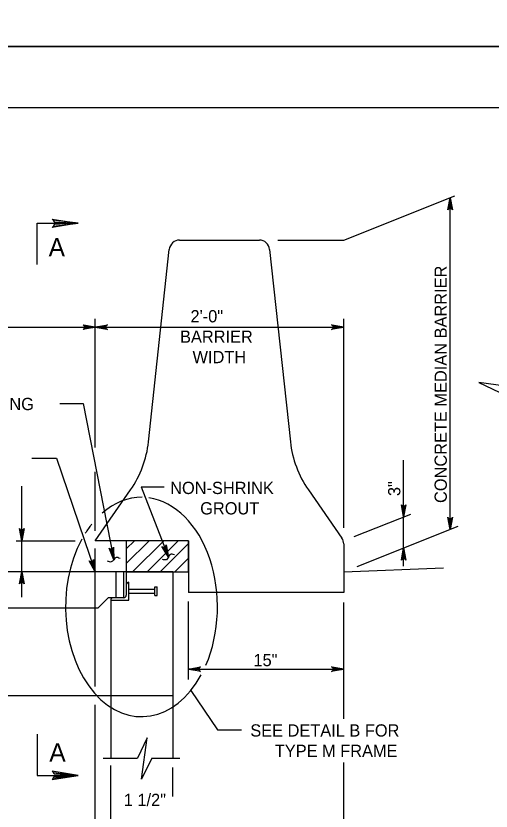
# Model space of a CAD drawing. Extents: x 2087776 to 2104538, y 970919 to 982612.
# Drawn here: x 2100038 to 2100420, y 976151 to 976790 of the extents above; entities that cross this region are included whole.
import ezdxf

# ---------------------------------------------------------------- set-up
doc = ezdxf.new("R2010")
doc.units = 0
doc.layers.add('1', color=7, linetype='Continuous')
doc.layers.add('PLT-BNDY', color=7, linetype='Continuous')

msp = doc.modelspace()

# ---------------------------------------------------------------- linework, layer by layer
at = {"layer": '1'}
for p, q in [((2100301.79, 976610.12), (2100391.14, 976645.62)), ((2100387.4, 976377.46), (2100387.4, 976644.13)), ((2100169.69, 976610.12), (2100233.89, 976610.12)), ((2100248.79, 976610.12), (2100301.79, 976610.12)), ((2100144.71, 976447.97), (2100161.41, 976602.68)), ((2100242.18, 976602.68), (2100258.88, 976447.97)), ((2100101.79, 976443.41), (2100101.79, 976546.94)), ((2100301.79, 976378.69), (2100301.79, 976546.94)), ((2099901.79, 976540.13), (2100101.79, 976540.13)), ((2100101.79, 976540.13), (2100301.79, 976540.13)), ((2100073.47, 976478.78), (2100092.2, 976478.78)), ((2100092.2, 976478.78), (2100116.73, 976353.17)), ((2100050.84, 976434.83), (2100070.67, 976434.83)), ((2100070.67, 976434.83), (2100101.79, 976343.45)), ((2100349.96, 976348.05), (2100349.96, 976433.16)), ((2100101.79, 976376.26), (2100101.79, 976423.89)), ((2100042.79, 976323.09), (2100042.79, 976412.2)), ((2100101.79, 976368.45), (2100130.24, 976409.29)), ((2100138.68, 976411.71), (2100157.42, 976411.71)), ((2100138.68, 976411.71), (2100160.69, 976355.3)), ((2100273.35, 976409.29), (2100300.3, 976370.59)), ((2100310.25, 976371.81), (2100355.72, 976389.88)), ((2100312.6, 976347.74), (2100393.93, 976380.06)), ((2100038.16, 976368.45), (2100085.61, 976368.45)), ((2100176.79, 976368.45), (2100101.79, 976368.45)), ((2100126.79, 976350.12), (2100145.12, 976368.45)), ((2100126.79, 976361.9), (2100133.34, 976368.45)), ((2100131.9, 976343.45), (2100156.9, 976368.45)), ((2100143.68, 976343.45), (2100168.68, 976368.45)), ((2100154.02, 976343.45), (2100176.79, 976366.22)), ((2100176.79, 976368.45), (2100176.79, 976326.78)), ((2100301.79, 976365.83), (2100301.79, 976326.78)), ((2100101.79, 976251.17), (2100101.79, 976362.06)), ((2100165.8, 976343.45), (2100176.79, 976354.44)), ((2100164.29, 976343.45), (2099864.29, 976343.45)), ((2100118.46, 976343.45), (2100118.46, 976322.61)), ((2100124.71, 976343.45), (2100124.71, 976322.61)), ((2100126.79, 976343.45), (2100126.79, 976333.03)), ((2100164.29, 976343.45), (2100164.29, 976193.61)), ((2100301.79, 976343.45), (2100382, 976346.66)), ((2100126.79, 976333.03), (2100126.79, 976324.7)), ((2100128.88, 976320.53), (2100128.88, 976335.11)), ((2100149.79, 976324.26), (2100149.79, 976331.38)), ((2100149.79, 976331.38), (2100151.79, 976331.38)), ((2100151.79, 976324.26), (2100151.79, 976331.38)), ((2100128.88, 976329.38), (2100149.79, 976329.38)), ((2100128.88, 976326.26), (2100149.79, 976326.26)), ((2100149.79, 976324.26), (2100151.79, 976324.26)), ((2100301.79, 976326.78), (2100176.79, 976326.78)), ((2100112.21, 976322.61), (2100103.88, 976314.28)), ((2100116.37, 976322.61), (2100112.21, 976322.61)), ((2100114.29, 976320.53), (2100114.29, 976243.61)), ((2100114.29, 976320.53), (2100128.88, 976320.53)), ((2100124.71, 976322.62), (2100116.37, 976322.62)), ((2100176.79, 976256.83), (2100176.79, 976319.66)), ((2100301.79, 976225.26), (2100301.79, 976318.83)), ((2100103.88, 976314.28), (2099924.7, 976314.28)), ((2100176.79, 976265.16), (2100301.79, 976265.16)), ((2100178.77, 976248.08), (2100200.09, 976216.49)), ((2100164.29, 976243.61), (2099864.29, 976243.61)), ((2100114.29, 976243.61), (2100114.29, 976193.61)), ((2100101.79, 976095.62), (2100101.79, 976236.51)), ((2100200.09, 976216.49), (2100219.59, 976216.49)), ((2100108.16, 976193.61), (2100135.94, 976193.61)), ((2100147.49, 976193.61), (2100169.85, 976193.61)), ((2100301.79, 976095.62), (2100301.79, 976190.11)), ((2100114.29, 976140.51), (2100114.29, 976187.81)), ((2100164.29, 976162.8), (2100164.29, 976186.07))]:
    msp.add_line(p, q, dxfattribs=at)
for points in [[(2101519.11, 974866.19), (2101519.11, 976716.58), (2098940.37, 976716.58), (2098940.37, 974866.19), (2101519.11, 974866.19), (2101519.11, 974952.67), (2100862.94, 974952.67), (2100862.94, 975164.86), (2101519.11, 975164.86), (2101519.11, 975259.89), (2100862.94, 975259.89), (2100862.94, 974866.19), (2101121.48, 974866.19), (2101121.48, 974952.67), (2101121.48, 974866.19), (2101374.1, 974866.19), (2101374.1, 974952.67), (2101374.1, 974912.26), (2101519.11, 974912.26)], [(2100387.4, 976644.13), (2100389.24, 976634.35), (2100388.98, 976634.73), (2100388.72, 976635.1), (2100388.39, 976635.3), (2100388.06, 976635.49), (2100387.73, 976635.55), (2100387.4, 976635.6), (2100387.08, 976635.55), (2100386.75, 976635.49), (2100386.42, 976635.3), (2100386.09, 976635.1), (2100385.83, 976634.73), (2100385.57, 976634.35), (2100387.4, 976644.13), (2100385.83, 976634.73), (2100386.09, 976635.1), (2100387.4, 976644.13), (2100386.42, 976635.3), (2100386.75, 976635.49), (2100387.4, 976644.13), (2100387.08, 976635.55), (2100387.4, 976635.6), (2100387.4, 976644.13), (2100387.73, 976635.55), (2100388.06, 976635.49), (2100387.4, 976644.13), (2100388.39, 976635.3), (2100388.72, 976635.1), (2100387.4, 976644.13), (2100388.98, 976634.73)], [(2100068.11, 976626.2), (2100068.86, 976624.76), (2100088.14, 976623.69), (2100068.11, 976626.2), (2100067.09, 976627.08), (2100088.14, 976623.69), (2100068.87, 976622.74), (2100068.17, 976621.3), (2100088.14, 976623.69), (2100067.09, 976620.35), (2100068.17, 976621.3)], [(2100055.06, 976590.62), (2100055.06, 976623.69), (2100088.14, 976623.69)], [(2100101.79, 976540.13), (2100092.01, 976538.29), (2100092.38, 976538.55), (2100092.76, 976538.81), (2100092.96, 976539.14), (2100093.15, 976539.47), (2100093.21, 976539.8), (2100093.26, 976540.13), (2100093.21, 976540.45), (2100093.15, 976540.78), (2100092.96, 976541.11), (2100092.76, 976541.44), (2100092.38, 976541.7), (2100092.01, 976541.96), (2100101.79, 976540.13), (2100092.38, 976541.7), (2100092.76, 976541.44), (2100101.79, 976540.13), (2100092.96, 976541.11), (2100093.15, 976540.78), (2100101.79, 976540.13), (2100093.21, 976540.45), (2100093.26, 976540.13), (2100101.79, 976540.13), (2100093.21, 976539.8), (2100093.15, 976539.47), (2100101.79, 976540.13), (2100092.96, 976539.14), (2100092.76, 976538.81), (2100101.79, 976540.13), (2100092.38, 976538.55)], [(2100101.79, 976540.13), (2100111.58, 976541.96), (2100111.2, 976541.7), (2100110.82, 976541.44), (2100110.63, 976541.11), (2100110.44, 976540.78), (2100110.38, 976540.45), (2100110.32, 976540.13), (2100110.38, 976539.8), (2100110.44, 976539.47), (2100110.63, 976539.14), (2100110.82, 976538.81), (2100111.2, 976538.55), (2100111.58, 976538.29), (2100101.79, 976540.13), (2100111.2, 976538.55), (2100110.82, 976538.81), (2100101.79, 976540.13), (2100110.63, 976539.14), (2100110.44, 976539.47), (2100101.79, 976540.13), (2100110.38, 976539.8), (2100110.32, 976540.13), (2100101.79, 976540.13), (2100110.38, 976540.45), (2100110.44, 976540.78), (2100101.79, 976540.13), (2100110.63, 976541.11), (2100110.82, 976541.44), (2100101.79, 976540.13), (2100111.2, 976541.7)], [(2100301.79, 976540.13), (2100292.01, 976538.29), (2100292.38, 976538.55), (2100292.76, 976538.81), (2100292.96, 976539.14), (2100293.15, 976539.47), (2100293.21, 976539.8), (2100293.26, 976540.13), (2100293.21, 976540.45), (2100293.15, 976540.78), (2100292.96, 976541.11), (2100292.76, 976541.44), (2100292.38, 976541.7), (2100292.01, 976541.96), (2100301.79, 976540.13), (2100292.38, 976541.7), (2100292.76, 976541.44), (2100301.79, 976540.13), (2100292.96, 976541.11), (2100293.15, 976540.78), (2100301.79, 976540.13), (2100293.21, 976540.45), (2100293.26, 976540.13), (2100301.79, 976540.13), (2100293.21, 976539.8), (2100293.15, 976539.47), (2100301.79, 976540.13), (2100292.96, 976539.14), (2100292.76, 976538.81), (2100301.79, 976540.13), (2100292.38, 976538.55)], [(2100426.75, 976499.53), (2100443.76, 976491.21), (2100410.47, 976495.73), (2100426.75, 976487.99)], [(2100349.96, 976387.59), (2100348.13, 976397.37), (2100348.39, 976396.99), (2100348.65, 976396.62), (2100348.98, 976396.42), (2100349.3, 976396.23), (2100349.63, 976396.17), (2100349.96, 976396.12), (2100350.29, 976396.17), (2100350.62, 976396.23), (2100350.94, 976396.42), (2100351.27, 976396.62), (2100351.53, 976396.99), (2100351.8, 976397.37), (2100349.96, 976387.59), (2100351.53, 976396.99), (2100351.27, 976396.62), (2100349.96, 976387.59), (2100350.94, 976396.42), (2100350.62, 976396.23), (2100349.96, 976387.59), (2100350.29, 976396.17), (2100349.96, 976396.12), (2100349.96, 976387.59), (2100349.63, 976396.17), (2100349.3, 976396.23), (2100349.96, 976387.59), (2100348.98, 976396.42), (2100348.65, 976396.62), (2100349.96, 976387.59), (2100348.39, 976396.99)], [(2100387.4, 976377.46), (2100385.57, 976387.25), (2100385.83, 976386.87), (2100386.09, 976386.5), (2100386.42, 976386.3), (2100386.75, 976386.11), (2100387.08, 976386.05), (2100387.4, 976385.99), (2100387.73, 976386.05), (2100388.06, 976386.11), (2100388.39, 976386.3), (2100388.72, 976386.5), (2100388.98, 976386.87), (2100389.24, 976387.25), (2100387.4, 976377.46), (2100388.98, 976386.87), (2100388.72, 976386.5), (2100387.4, 976377.46), (2100388.39, 976386.3), (2100388.06, 976386.11), (2100387.4, 976377.46), (2100387.73, 976386.05), (2100387.4, 976385.99), (2100387.4, 976377.46), (2100387.08, 976386.05), (2100386.75, 976386.11), (2100387.4, 976377.46), (2100386.42, 976386.3), (2100386.09, 976386.5), (2100387.4, 976377.46), (2100385.83, 976386.87)], [(2100042.79, 976368.45), (2100040.96, 976378.23), (2100041.22, 976377.86), (2100041.48, 976377.48), (2100041.81, 976377.28), (2100042.13, 976377.09), (2100042.46, 976377.03), (2100042.79, 976376.98), (2100043.12, 976377.03), (2100043.45, 976377.09), (2100043.77, 976377.28), (2100044.1, 976377.48), (2100044.36, 976377.86), (2100044.62, 976378.23), (2100042.79, 976368.45), (2100044.36, 976377.86), (2100044.1, 976377.48), (2100042.79, 976368.45), (2100043.77, 976377.28), (2100043.45, 976377.09), (2100042.79, 976368.45), (2100043.12, 976377.03), (2100042.79, 976376.98), (2100042.79, 976368.45), (2100042.46, 976377.03), (2100042.13, 976377.09), (2100042.79, 976368.45), (2100041.81, 976377.28), (2100041.48, 976377.48), (2100042.79, 976368.45), (2100041.22, 976377.86)], [(2100116.73, 976353.16), (2100113.04, 976362.41), (2100113.37, 976362.09), (2100113.7, 976361.77), (2100114.06, 976361.64), (2100114.42, 976361.51), (2100114.75, 976361.52), (2100115.08, 976361.53), (2100115.4, 976361.65), (2100115.71, 976361.77), (2100115.99, 976362.02), (2100116.28, 976362.28), (2100116.46, 976362.7), (2100116.64, 976363.12), (2100116.73, 976353.16), (2100116.46, 976362.7), (2100116.28, 976362.28), (2100116.73, 976353.16), (2100115.99, 976362.02), (2100115.71, 976361.77), (2100116.73, 976353.16), (2100115.4, 976361.65), (2100115.08, 976361.53), (2100116.73, 976353.16), (2100114.75, 976361.52), (2100114.42, 976361.51), (2100116.73, 976353.16), (2100114.06, 976361.64), (2100113.7, 976361.77), (2100116.73, 976353.16), (2100113.37, 976362.09)], [(2100160.69, 976355.3), (2100155.42, 976363.75), (2100156.18, 976363.24), (2100156.94, 976363.11), (2100157.59, 976363.25), (2100158.16, 976363.59), (2100158.63, 976364.19), (2100158.84, 976365.08), (2100160.69, 976355.3), (2100158.63, 976364.19), (2100158.16, 976363.59), (2100160.69, 976355.3), (2100157.59, 976363.25), (2100156.94, 976363.11), (2100160.69, 976355.3), (2100156.18, 976363.24)], [(2100349.96, 976362.59), (2100351.8, 976352.8), (2100351.53, 976353.18), (2100351.27, 976353.55), (2100350.94, 976353.75), (2100350.62, 976353.94), (2100350.29, 976354), (2100349.96, 976354.06), (2100349.63, 976354), (2100349.3, 976353.94), (2100348.98, 976353.75), (2100348.65, 976353.55), (2100348.39, 976353.18), (2100348.13, 976352.8), (2100349.96, 976362.59), (2100348.39, 976353.18), (2100348.65, 976353.55), (2100349.96, 976362.59), (2100348.98, 976353.75), (2100349.3, 976353.94), (2100349.96, 976362.59), (2100349.63, 976354), (2100349.96, 976354.06), (2100349.96, 976362.59), (2100350.29, 976354), (2100350.62, 976353.94), (2100349.96, 976362.59), (2100350.94, 976353.75), (2100351.27, 976353.55), (2100349.96, 976362.59), (2100351.53, 976353.18)], [(2100101.79, 976343.45), (2100096.9, 976352.12), (2100097.27, 976351.85), (2100097.64, 976351.57), (2100098.01, 976351.5), (2100098.39, 976351.42), (2100098.71, 976351.47), (2100099.04, 976351.52), (2100099.34, 976351.68), (2100099.63, 976351.84), (2100099.88, 976352.13), (2100100.12, 976352.42), (2100100.25, 976352.86), (2100100.38, 976353.3), (2100101.79, 976343.45), (2100100.25, 976352.86), (2100100.12, 976352.42), (2100101.79, 976343.45), (2100099.88, 976352.13), (2100099.63, 976351.84), (2100101.79, 976343.45), (2100099.34, 976351.68), (2100099.04, 976351.52), (2100101.79, 976343.45), (2100098.71, 976351.47), (2100098.39, 976351.42), (2100101.79, 976343.45), (2100098.01, 976351.5), (2100097.64, 976351.57), (2100101.79, 976343.45), (2100097.27, 976351.85)], [(2100042.79, 976343.45), (2100044.62, 976333.66), (2100044.36, 976334.04), (2100044.1, 976334.42), (2100043.77, 976334.61), (2100043.45, 976334.8), (2100043.12, 976334.86), (2100042.79, 976334.92), (2100042.46, 976334.86), (2100042.13, 976334.8), (2100041.81, 976334.61), (2100041.48, 976334.42), (2100041.22, 976334.04), (2100040.96, 976333.66), (2100042.79, 976343.45), (2100041.22, 976334.04), (2100041.48, 976334.42), (2100042.79, 976343.45), (2100041.81, 976334.61), (2100042.13, 976334.8), (2100042.79, 976343.45), (2100042.46, 976334.86), (2100042.79, 976334.92), (2100042.79, 976343.45), (2100043.12, 976334.86), (2100043.45, 976334.8), (2100042.79, 976343.45), (2100043.77, 976334.61), (2100044.1, 976334.42), (2100042.79, 976343.45), (2100044.36, 976334.04)], [(2100176.79, 976265.16), (2100186.58, 976266.99), (2100185.82, 976266.47), (2100185.44, 976265.81), (2100185.32, 976265.16), (2100185.44, 976264.5), (2100185.82, 976263.84), (2100186.58, 976263.32), (2100176.79, 976265.16), (2100185.82, 976263.84), (2100185.44, 976264.5), (2100176.79, 976265.16), (2100185.32, 976265.16), (2100185.44, 976265.81), (2100176.79, 976265.16), (2100185.82, 976266.47)], [(2100301.79, 976265.16), (2100292.01, 976263.32), (2100292.38, 976263.58), (2100292.76, 976263.84), (2100292.96, 976264.17), (2100293.15, 976264.5), (2100293.21, 976264.83), (2100293.26, 976265.16), (2100293.21, 976265.48), (2100293.15, 976265.81), (2100292.96, 976266.14), (2100292.76, 976266.47), (2100292.38, 976266.73), (2100292.01, 976266.99), (2100301.79, 976265.16), (2100292.38, 976266.73), (2100292.76, 976266.47), (2100301.79, 976265.16), (2100292.96, 976266.14), (2100293.15, 976265.81), (2100301.79, 976265.16), (2100293.21, 976265.48), (2100293.26, 976265.16), (2100301.79, 976265.16), (2100293.21, 976264.83), (2100293.15, 976264.5), (2100301.79, 976265.16), (2100292.96, 976264.17), (2100292.76, 976263.84), (2100301.79, 976265.16), (2100292.38, 976263.58)], [(2100055.06, 976212.78), (2100055.06, 976179.71), (2100088.14, 976179.71)], [(2100147.48, 976193.61), (2100139.15, 976176.6), (2100143.68, 976209.9), (2100135.94, 976193.61)], [(2100068.11, 976177.2), (2100068.86, 976178.65), (2100088.14, 976179.71), (2100068.11, 976177.2), (2100067.09, 976176.32), (2100088.14, 976179.71), (2100068.87, 976180.67), (2100068.17, 976182.1), (2100088.14, 976179.71), (2100067.09, 976183.06), (2100068.17, 976182.1)]]:
    msp.add_lwpolyline(points, dxfattribs=at)
msp.add_lwpolyline([(2100126.79, 976343.45), (2100176.79, 976343.45), (2100176.79, 976368.45), (2100126.79, 976368.45)], close=True, dxfattribs=at)
for centre, radius, start, end in [((2100169.69, 976601.79), 8.33, 90, 173.83926), ((2100233.89, 976601.79), 8.33, 6.16074, 90), ((2100061.86, 976456.91), 83.33, 325.1407, 353.83926), ((2100341.72, 976456.91), 83.33, 186.16074, 214.8593), ((2100293.46, 976365.83), 8.33, 0, 34.8593), ((2100128.88, 976333.03), 2.08, 90, 180), ((2100124.71, 976324.7), 2.08, 270, 0), ((2100116.37, 976320.53), 2.08, 90, 180)]:
    msp.add_arc(centre, radius, start, end, dxfattribs=at)
for start_param, end_param in [(3.133963, 3.686554), (1.010873, 3.043169), (3.858512, 3.974108), (4.047235, 7.187845)]:
    msp.add_ellipse((2100139.06, 976315.12), major_axis=(0, -88.19), ratio=0.693116, start_param=start_param, end_param=end_param, dxfattribs=at)
for points in [[(2100165.49, 976357.06), (2100162.3, 976357.44), (2100159.06, 976353.14), (2100155.96, 976353.39)], [(2100121.77, 976354.04), (2100118.7, 976354.98), (2100114.74, 976351.32), (2100111.74, 976352.11)]]:
    msp.add_spline(points, degree=3, dxfattribs=at)
at = {"layer": 'PLT-BNDY'}
for points in [[(2098812.42, 978714.61), (2101571.61, 978714.61), (2101571.61, 976765.79), (2098812.42, 976765.79)], [(2098812.42, 976765.79), (2101571.61, 976765.79), (2101571.61, 974816.97), (2098812.42, 974816.97)]]:
    msp.add_lwpolyline(points, close=True, dxfattribs=at)

# ---------------------------------------------------------------- texts
at = {"layer": '1'}
for s, height, p in [('A', 14.76, (2100064.35, 976597)), ('2\'-0"', 9.843, (2100178.5, 976543.99)), ('BARRIER', 9.843, (2100170.09, 976527.59)), ('WIDTH', 9.843, (2100180.13, 976511.18)), ('FORMED OPENING', 9.8425, (2099931.11, 976473.44)), ('NON-SHRINK', 9.843, (2100162.14, 976405.96)), ('GROUT', 9.843, (2100186.28, 976389.55)), ('15"', 9.843, (2100229.17, 976267.54)), ('SEE DETAIL B FOR', 9.8425, (2100226.61, 976210.95)), ('A', 14.76, (2100064.89, 976190.82)), ('TYPE M FRAME', 9.8425, (2100246.33, 976194.54)), ('1 1/2"', 9.843, (2100124.8, 976155.11))]:
    msp.add_text(s, height=height, dxfattribs=at).set_placement(p)
for s, height, p in [('CONCRETE MEDIAN BARRIER', 9.8425, (2100384.72, 976398.74)), ('3"', 9.843, (2100347.33, 976404.32))]:
    msp.add_text(s, height=height, rotation=90, dxfattribs=at).set_placement(p)

doc.saveas('drawing.dxf')
